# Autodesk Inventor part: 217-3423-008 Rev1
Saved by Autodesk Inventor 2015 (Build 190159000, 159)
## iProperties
Created: 2014-11
Part Number: 217-3423-008 Rev1
Material: Generic
Document SubType Name: Modeling
Designer: User
Density: 1 g/cm^3
Appearance: Default
Author: User
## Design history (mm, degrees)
node "217-3423-008 Rev1.ipt1"
node "Chamfer1"
node "Base1"
